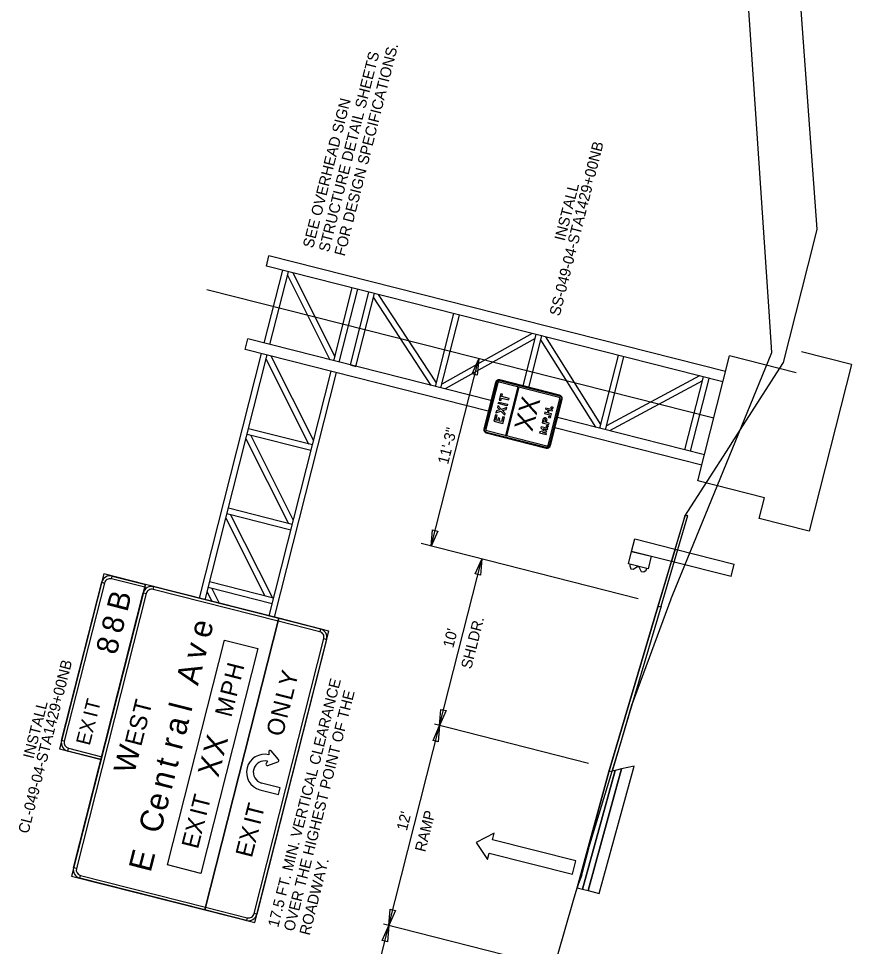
# Model space of a CAD drawing. Extents: x 670003 to 670131, y 737764 to 738002.
# Drawn here: x 670064.8 to 670113.2, y 737890.5 to 737944.5 of the extents above; entities that cross this region are included whole.
import ezdxf

# ---------------------------------------------------------------- set-up
doc = ezdxf.new("R2010")
doc.units = 0
for name, color, linetype in [('R_Alt Surface', 7, 'Continuous'), ('R_Exist Surface', 7, 'Continuous'), ('R_Fin Surface', 7, 'Continuous'), ('R_Guardrail', 7, 'Continuous'), ('R_Horz Alg Annot', 7, 'Continuous'), ('R_MOT', 7, 'Continuous'), ('R_SIGN', 7, 'Continuous'), ('R_SIGN_ANNOT', 7, 'Continuous')]:
    doc.layers.add(name, color=color, linetype=linetype)

msp = doc.modelspace()

# ---------------------------------------------------------------- linework, layer by layer
at = {"layer": 'R_Alt Surface'}
for points in [[(670097.563, 737893.862), (670097.887, 737893.78), (670099.826, 737900.86), (670099.462, 737900.78)], [(670097.887, 737893.78), (670098.533, 737893.617), (670100.555, 737901.019), (670099.826, 737900.86)]]:
    msp.add_lwpolyline(points, close=True, dxfattribs=at)
at = {"layer": 'R_Exist Surface'}
msp.add_lwpolyline([(670096.104, 737889.98), (670097.035, 737893.228), (670097.24, 737893.944), (670097.24, 737893.944), (670097.285, 737894.053), (670097.514, 737894.659), (670097.566, 737894.848), (670097.93, 737896.249), (670097.945, 737896.326), (670098.182, 737897.114), (670099.492, 737901.429), (670099.768, 737902.328), (670100.454, 737904.642), (670100.458, 737904.668), (670102.71, 737910.768), (670102.713, 737910.776), (670102.77, 737910.917), (670108.58, 737925.092), (670108.418, 737927.472), (670107.207, 737945.304)], dxfattribs=at)
at = {"layer": 'R_Fin Surface'}
for points in [[(670097.24, 737893.944), (670099.098, 737900.7), (670101.946, 737910.296), (670103.442, 737915.34), (670103.51, 737915.569), (670106.099, 737919.607), (670106.256, 737919.851), (670109.028, 737924.175), (670109.243, 737924.51), (670111.027, 737931.54), (670111.211, 737932.265), (670109.788, 737951.654), (670109.54, 737955.045)], [(670101.946, 737910.296), (670099.098, 737900.7), (670097.24, 737893.944)]]:
    msp.add_lwpolyline(points, dxfattribs=at)
for points in [[(670101.946, 737910.296), (670102.128, 737910.336), (670103.692, 737915.609), (670103.51, 737915.569)], [(670099.098, 737900.7), (670101.946, 737910.296), (670102.128, 737910.336), (670099.28, 737900.74)], [(670097.24, 737893.944), (670097.563, 737893.862), (670099.462, 737900.78), (670099.098, 737900.7)]]:
    msp.add_lwpolyline(points, close=True, dxfattribs=at)
at = {"layer": 'R_Guardrail'}
for points in [[(670100.412, 737913.522), (670100.596, 737914.249), (670102.942, 737913.654), (670102.729, 737912.935)], [(670100.227, 737912.795), (670100.412, 737913.522), (670101.557, 737913.232), (670101.372, 737912.505)], [(670100.304, 737912.776), (670100.301, 737912.675), (670100.362, 737912.512), (670100.501, 737912.476), (670100.752, 737912.648), (670100.841, 737912.626), (670100.979, 737912.355), (670101.118, 737912.32), (670101.251, 737912.434), (670101.296, 737912.524)]]:
    msp.add_lwpolyline(points, close=True, dxfattribs=at)
for points in [[(670106.199, 737912.055), (670102.729, 737912.935), (670102.942, 737913.654), (670106.383, 737912.782)], [(670106.199, 737912.055), (670106.383, 737912.782)]]:
    msp.add_lwpolyline(points, dxfattribs=at)
at = {"layer": 'R_Horz Alg Annot'}
for p, q in [((670088.751, 737913.823), (670091.517, 737924.728)), ((670100.796, 737910.768), (670088.176, 737913.969)), ((670089.242, 737903.382), (670091.7, 737913.075)), ((670086.291, 737891.75), (670089.242, 737903.382)), ((670097.915, 737901.182), (670088.939, 737903.459)), ((670083.356, 737880.175), (670086.291, 737891.75)), ((670094.965, 737889.55), (670085.989, 737891.827))]:
    msp.add_line(p, q, dxfattribs=at)
for points in [[(670091.135, 737923.857), (670091.517, 737924.728), (670091.438, 737923.781)], [(670089.133, 737914.693), (670088.751, 737913.823), (670088.83, 737914.77)], [(670091.318, 737912.205), (670091.7, 737913.075), (670091.621, 737912.128)], [(670089.623, 737904.252), (670089.242, 737903.382), (670089.321, 737904.329)], [(670088.86, 737902.512), (670089.242, 737903.382), (670089.163, 737902.435)], [(670086.673, 737892.621), (670086.291, 737891.75), (670086.37, 737892.697)], [(670085.91, 737890.88), (670086.291, 737891.75), (670086.212, 737890.803)]]:
    msp.add_lwpolyline(points, close=True, dxfattribs=at)
at = {"layer": 'R_MOT'}
for p, q in [((670092.419, 737897.134), (670091.372, 737896.574)), ((670092.321, 737896.746), (670092.419, 737897.134)), ((670091.372, 737896.574), (670092.026, 737895.583)), ((670097.164, 737895.518), (670092.321, 737896.746)), ((670092.026, 737895.583), (670092.124, 737895.97)), ((670092.124, 737895.97), (670096.967, 737894.742)), ((670096.967, 737894.742), (670097.164, 737895.518))]:
    msp.add_line(p, q, dxfattribs=at)
at = {"layer": 'R_SIGN'}
for p, q in [((670079.164, 737930.117), (670079.318, 737930.723)), ((670105.879, 737923.987), (670079.318, 737930.723)), ((670079.046, 737925.634), (670080.121, 737929.875)), ((670105.725, 737923.381), (670079.164, 737930.117)), ((670079.369, 737925.552), (670080.444, 737929.793)), ((670080.393, 737929.593), (670082.866, 737924.665)), ((670080.707, 737929.726), (670083.148, 737924.861)), ((670083.084, 737924.61), (670084.16, 737928.85)), ((670083.407, 737924.528), (670084.483, 737928.768)), ((670105.187, 737921.261), (670075.695, 737928.74)), ((670084.054, 737924.364), (670085.129, 737928.604)), ((670084.377, 737924.282), (670085.452, 737928.523)), ((670088.761, 737923.17), (670085.397, 737928.303)), ((670089.056, 737923.329), (670085.692, 737928.462)), ((670089.001, 737923.109), (670090.076, 737927.35)), ((670089.324, 737923.027), (670090.399, 737927.268)), ((670094.627, 737926.196), (670089.38, 737923.25)), ((670094.103, 737923.145), (670094.862, 737926.136)), ((670094.426, 737923.063), (670095.185, 737926.054)), ((670077.935, 737925.271), (670078.089, 737925.877)), ((670092.227, 737922.291), (670078.089, 737925.877)), ((670094.805, 737925.913), (670089.559, 737922.968)), ((670098.337, 737920.741), (670095.128, 737925.831)), ((670098.628, 737920.905), (670095.42, 737925.995)), ((670075.281, 737910.791), (670078.892, 737925.028)), ((670092.074, 737921.685), (670077.935, 737925.271)), ((670113.202, 737924.386), (670110.294, 737925.124)), ((670075.604, 737910.709), (670079.215, 737924.946)), ((670079.151, 737924.694), (670081.624, 737919.766)), ((670079.433, 737924.891), (670081.906, 737919.963)), ((670098.572, 737920.682), (670099.647, 737924.922)), ((670098.895, 737920.6), (670099.97, 737924.84)), ((670104.265, 737917.626), (670106.109, 737924.895)), ((670109.986, 737923.912), (670106.109, 737924.895)), ((670079.32, 737909.767), (670082.931, 737924.004)), ((670079.643, 737909.685), (670083.254, 737923.922)), ((670084.054, 737924.364), (670084.377, 737924.282)), ((670113.202, 737924.386), (670110.743, 737914.693)), ((670096.196, 737922.478), (670092.706, 737923.363)), ((670096.216, 737922.558), (670092.726, 737923.444)), ((670092.736, 737923.484), (670092.736, 737923.484)), ((670096.226, 737922.599), (670092.736, 737923.484)), ((670096.228, 737922.606), (670092.738, 737923.492)), ((670104.355, 737923.728), (670098.95, 737920.819)), ((670104.538, 737923.448), (670099.134, 737920.539)), ((670103.519, 737919.427), (670104.594, 737923.668)), ((670103.842, 737919.345), (670104.917, 737923.586)), ((670092.496, 737923.349), (670091.813, 737920.657)), ((670092.504, 737923.346), (670091.821, 737920.655)), ((670092.544, 737923.336), (670091.861, 737920.644)), ((670092.625, 737923.316), (670091.942, 737920.624)), ((670092.504, 737923.346), (670092.504, 737923.346)), ((670093.794, 737923.087), (670093.079, 737920.267)), ((670093.794, 737923.087), (670093.079, 737920.267)), ((670093.794, 737923.087), (670093.079, 737920.267)), ((670093.16, 737920.247), (670093.875, 737923.067)), ((670093.16, 737920.247), (670093.875, 737923.067)), ((670093.16, 737920.247), (670093.875, 737923.067)), ((670093.875, 737923.067), (670093.794, 737923.087)), ((670093.875, 737923.067), (670093.794, 737923.087)), ((670093.875, 737923.067), (670093.794, 737923.087)), ((670096.228, 737922.606), (670093.867, 737923.205)), ((670095.562, 737919.707), (670096.244, 737922.398)), ((670095.642, 737919.686), (670096.325, 737922.377)), ((670095.683, 737919.675), (670096.365, 737922.367)), ((670095.691, 737919.673), (670096.373, 737922.365)), ((670096.226, 737922.599), (670096.226, 737922.598)), ((670096.365, 737922.367), (670096.365, 737922.367)), ((670104.649, 737919.14), (670096.105, 737921.307)), ((670091.821, 737920.655), (670091.821, 737920.655)), ((670095.421, 737921.154), (670095.39, 737921.029)), ((670095.458, 737921.012), (670095.489, 737921.137)), ((670104.496, 737918.534), (670095.943, 737920.703)), ((670081.758, 737919.382), (670078.043, 737920.324)), ((670081.842, 737919.711), (670078.126, 737920.653)), ((670078.261, 737920.269), (670080.733, 737915.341)), ((670091.958, 737920.415), (670095.448, 737919.53)), ((670091.96, 737920.423), (670095.45, 737919.538)), ((670091.96, 737920.423), (670091.96, 737920.423)), ((670091.97, 737920.463), (670095.46, 737919.578)), ((670091.991, 737920.543), (670095.48, 737919.658)), ((670093.079, 737920.267), (670093.16, 737920.247)), ((670093.079, 737920.267), (670093.16, 737920.247)), ((670093.079, 737920.267), (670093.16, 737920.247)), ((670077.979, 737920.072), (670080.452, 737915.144)), ((670095.642, 737919.686), (670095.561, 737919.706)), ((670095.562, 737919.707), (670095.642, 737919.686)), ((670095.691, 737919.673), (670095.683, 737919.675)), ((670095.683, 737919.675), (670095.683, 737919.675)), ((670095.683, 737919.675), (670095.691, 737919.673)), ((670095.45, 737919.538), (670095.45, 737919.538)), ((670108.143, 737916.642), (670104.265, 737917.626)), ((670107.835, 737915.431), (670108.143, 737916.642)), ((670080.67, 737915.089), (670076.954, 737916.031)), ((670076.806, 737915.45), (670079.078, 737910.924)), ((670080.586, 737914.759), (670076.87, 737915.702)), ((670077.088, 737915.646), (670079.514, 737910.813)), ((670110.743, 737914.693), (670107.835, 737915.431)), ((670069.708, 737912.205), (670067.126, 737902.027)), ((670072.131, 737911.59), (670069.708, 737912.205)), ((670070.151, 737911.92), (670070.192, 737912.082)), ((670072.131, 737911.59), (670067.829, 737894.627)), ((670069.55, 737901.413), (670072.131, 737911.59)), ((670069.585, 737911.72), (670069.746, 737911.679)), ((670079.885, 737909.624), (670072.131, 737911.59)), ((670079.581, 737910.796), (670075.865, 737911.739)), ((670072.008, 737911.106), (670072.169, 737911.065)), ((670072.575, 737911.306), (670072.615, 737911.467)), ((670075.718, 737911.157), (670075.992, 737910.611)), ((670079.497, 737910.467), (670075.782, 737911.409)), ((670076, 737911.354), (670076.428, 737910.501)), ((670075.583, 737892.661), (670079.885, 737909.624)), ((670079.885, 737909.624), (670075.583, 737892.661)), ((670082.793, 737908.886), (670079.885, 737909.624)), ((670078.491, 737891.923), (670082.793, 737908.886)), ((670082.309, 737909.009), (670082.268, 737908.847)), ((670073.409, 737895.275), (670076.728, 737908.361)), ((670076.728, 737908.361), (670078.667, 737907.869)), ((670082.509, 737908.442), (670082.67, 737908.401)), ((670078.667, 737907.869), (670075.348, 737894.784)), ((670067.411, 737902.471), (670067.249, 737902.512)), ((670067.126, 737902.027), (670069.55, 737901.413)), ((670067.611, 737901.904), (670067.652, 737902.066)), ((670079.301, 737901.855), (670079.31, 737901.684)), ((670079.301, 737901.855), (670079.31, 737901.684)), ((670079.875, 737901.404), (670079.439, 737901.91)), ((670079.875, 737901.404), (670079.439, 737901.91)), ((670069.55, 737901.413), (670069.55, 737901.413)), ((670079.229, 737901.307), (670079.149, 737901.183)), ((670079.229, 737901.307), (670079.149, 737901.183)), ((670079.242, 737901.066), (670079.842, 737901.279)), ((670079.242, 737901.066), (670079.842, 737901.279)), ((670078.788, 737899.653), (670079.876, 737899.377)), ((670078.788, 737899.653), (670079.876, 737899.377)), ((670079.974, 737899.761), (670078.885, 737900.037)), ((670079.974, 737899.761), (670078.885, 737900.037)), ((670079.876, 737899.377), (670079.974, 737899.761)), ((670079.876, 737899.377), (670079.974, 737899.761)), ((670068.113, 737895.071), (670067.952, 737895.112)), ((670075.348, 737894.784), (670073.409, 737895.275)), ((670067.829, 737894.627), (670075.583, 737892.661)), ((670068.313, 737894.504), (670068.354, 737894.666)), ((670075.422, 737892.702), (670070.898, 737893.849)), ((670075.583, 737892.661), (670075.583, 737892.661)), ((670075.583, 737892.661), (670078.491, 737891.923)), ((670078.047, 737892.208), (670078.006, 737892.046)), ((670078.614, 737892.408), (670078.452, 737892.449)), ((670078.491, 737891.923), (670078.491, 737891.923))]:
    msp.add_line(p, q, dxfattribs=at)
for points in [[(670092.8, 737922.291), (670092.836, 737922.435), (670093.263, 737922.327), (670093.285, 737922.415), (670092.859, 737922.523), (670092.895, 737922.667), (670092.805, 737922.69), (670092.709, 737922.314)], [(670092.8, 737922.291), (670092.836, 737922.435), (670093.263, 737922.327), (670093.285, 737922.415), (670092.859, 737922.523), (670092.895, 737922.667), (670092.805, 737922.69), (670092.709, 737922.314)], [(670092.8, 737922.291), (670092.836, 737922.435), (670093.263, 737922.327), (670093.285, 737922.415), (670092.859, 737922.523), (670092.895, 737922.667), (670092.805, 737922.69), (670092.709, 737922.314)], [(670093.038, 737921.44), (670093.064, 737921.545), (670092.908, 737921.708), (670093.123, 737921.777), (670093.15, 737921.882), (670092.837, 737921.782), (670092.629, 737921.999), (670092.603, 737921.894), (670092.74, 737921.75), (670092.551, 737921.69), (670092.524, 737921.585), (670092.811, 737921.677)], [(670093.038, 737921.44), (670093.064, 737921.545), (670092.908, 737921.708), (670093.123, 737921.777), (670093.15, 737921.882), (670092.837, 737921.782), (670092.629, 737921.999), (670092.603, 737921.894), (670092.74, 737921.75), (670092.551, 737921.69), (670092.524, 737921.585), (670092.811, 737921.677)], [(670093.038, 737921.44), (670093.064, 737921.545), (670092.908, 737921.708), (670093.123, 737921.777), (670093.15, 737921.882), (670092.837, 737921.782), (670092.629, 737921.999), (670092.603, 737921.894), (670092.74, 737921.75), (670092.551, 737921.69), (670092.524, 737921.585), (670092.811, 737921.677)], [(670093.177, 737921.988), (670092.66, 737922.119), (670092.682, 737922.208), (670093.199, 737922.076)], [(670093.177, 737921.988), (670092.66, 737922.119), (670092.682, 737922.208), (670093.199, 737922.076)], [(670093.177, 737921.988), (670092.66, 737922.119), (670092.682, 737922.208), (670093.199, 737922.076)], [(670095.553, 737921.75), (670095.509, 737921.575), (670095.357, 737921.614), (670095.341, 737921.547), (670095.728, 737921.449), (670095.745, 737921.515), (670095.577, 737921.558), (670095.621, 737921.732), (670095.789, 737921.69), (670095.806, 737921.756), (670095.418, 737921.854), (670095.402, 737921.788)], [(670095.553, 737921.75), (670095.509, 737921.575), (670095.357, 737921.614), (670095.341, 737921.547), (670095.728, 737921.449), (670095.745, 737921.515), (670095.577, 737921.558), (670095.621, 737921.732), (670095.789, 737921.69), (670095.806, 737921.756), (670095.418, 737921.854), (670095.402, 737921.788)], [(670095.553, 737921.75), (670095.509, 737921.575), (670095.357, 737921.614), (670095.341, 737921.547), (670095.728, 737921.449), (670095.745, 737921.515), (670095.577, 737921.558), (670095.621, 737921.732), (670095.789, 737921.69), (670095.806, 737921.756), (670095.418, 737921.854), (670095.402, 737921.788)], [(670092.92, 737921.356), (670092.847, 737921.068), (670092.703, 737921.105), (670092.742, 737921.257), (670092.651, 737921.28), (670092.613, 737921.128), (670092.511, 737921.153), (670092.584, 737921.441), (670092.494, 737921.464), (670092.398, 737921.088), (670092.915, 737920.957), (670093.011, 737921.333)], [(670092.92, 737921.356), (670092.847, 737921.068), (670092.703, 737921.105), (670092.742, 737921.257), (670092.651, 737921.28), (670092.613, 737921.128), (670092.511, 737921.153), (670092.584, 737921.441), (670092.494, 737921.464), (670092.398, 737921.088), (670092.915, 737920.957), (670093.011, 737921.333)], [(670092.92, 737921.356), (670092.847, 737921.068), (670092.703, 737921.105), (670092.742, 737921.257), (670092.651, 737921.28), (670092.613, 737921.128), (670092.511, 737921.153), (670092.584, 737921.441), (670092.494, 737921.464), (670092.398, 737921.088), (670092.915, 737920.957), (670093.011, 737921.333)], [(670095.225, 737920.445), (670095.487, 737920.496), (670095.281, 737920.666), (670095.515, 737920.607), (670095.532, 737920.673), (670095.144, 737920.772), (670095.127, 737920.705), (670095.331, 737920.535), (670095.071, 737920.484), (670095.054, 737920.417), (670095.442, 737920.319), (670095.459, 737920.385)], [(670095.225, 737920.445), (670095.487, 737920.496), (670095.281, 737920.666), (670095.515, 737920.607), (670095.532, 737920.673), (670095.144, 737920.772), (670095.127, 737920.705), (670095.331, 737920.535), (670095.071, 737920.484), (670095.054, 737920.417), (670095.442, 737920.319), (670095.459, 737920.385)], [(670095.225, 737920.445), (670095.487, 737920.496), (670095.281, 737920.666), (670095.515, 737920.607), (670095.532, 737920.673), (670095.144, 737920.772), (670095.127, 737920.705), (670095.331, 737920.535), (670095.071, 737920.484), (670095.054, 737920.417), (670095.442, 737920.319), (670095.459, 737920.385)], [(670072.09, 737911.429), (670070.151, 737911.92), (670070.192, 737912.082), (670072.131, 737911.59), (670072.09, 737911.429)], [(670069.746, 737911.679), (670067.411, 737902.471), (670067.249, 737902.512), (670069.585, 737911.72), (670069.746, 737911.679)], [(670072.169, 737911.065), (670068.113, 737895.071), (670067.952, 737895.112), (670072.008, 737911.106), (670072.169, 737911.065)], [(670079.844, 737909.462), (670072.575, 737911.306), (670072.615, 737911.467), (670079.885, 737909.624), (670079.844, 737909.462)], [(670082.268, 737908.847), (670079.844, 737909.462), (670079.885, 737909.624), (670082.309, 737909.009), (670082.268, 737908.847)], [(670078.452, 737892.449), (670082.509, 737908.442), (670082.67, 737908.401), (670078.614, 737892.408), (670078.452, 737892.449)], [(670067.652, 737902.066), (670069.59, 737901.574), (670069.55, 737901.413), (670067.611, 737901.904), (670067.652, 737902.066)], [(670068.354, 737894.666), (670075.624, 737892.822), (670075.583, 737892.661), (670068.313, 737894.504), (670068.354, 737894.666)], [(670075.624, 737892.822), (670078.047, 737892.208), (670078.006, 737892.046), (670075.583, 737892.661), (670075.624, 737892.822)]]:
    msp.add_lwpolyline(points, close=True, dxfattribs=at)
for points in [[(670095.252, 737921.197), (670095.203, 737921.006), (670095.591, 737920.908), (670095.608, 737920.974), (670095.458, 737921.012)], [(670095.252, 737921.197), (670095.22, 737921.072), (670095.288, 737921.055), (670095.32, 737921.18)], [(670095.252, 737921.197), (670095.22, 737921.072), (670095.288, 737921.055), (670095.32, 737921.18)], [(670095.22, 737921.072), (670095.203, 737921.006), (670095.591, 737920.908), (670095.608, 737920.974), (670095.458, 737921.012), (670095.489, 737921.137)], [(670095.22, 737921.072), (670095.203, 737921.006), (670095.591, 737920.908), (670095.608, 737920.974), (670095.458, 737921.012), (670095.489, 737921.137)], [(670095.421, 737921.154), (670095.39, 737921.029), (670095.22, 737921.072)], [(670095.421, 737921.154), (670095.39, 737921.029), (670095.22, 737921.072)], [(670095.39, 737921.029), (670095.288, 737921.055), (670095.32, 737921.18)]]:
    msp.add_lwpolyline(points, dxfattribs=at)
for centre, radius, start, end in [((670070.069, 737911.597), 0.5, 75.7686, 165.7688), ((670070.069, 737911.597), 0.333, 75.7686, 165.7688), ((670072.493, 737910.983), 0.5, 75.7686, 165.7688), ((670072.493, 737910.983), 0.333, 75.7686, 165.7688), ((670082.186, 737908.524), 0.333, 345.7686, 75.7688), ((670082.186, 737908.524), 0.5, 345.7686, 75.7688), ((670067.734, 737902.389), 0.5, 165.7688, 255.7684), ((670067.734, 737902.389), 0.333, 165.7688, 255.7684), ((670079.379, 737901.859), 0.0785, 40.7767, 183.2283), ((670079.379, 737901.859), 0.0785, 40.7767, 183.2283), ((670079.06, 737900.666), 1.049, 76.1684, 254.9793), ((670079.06, 737900.666), 1.049, 76.1684, 254.9793), ((670079.063, 737900.671), 0.658, 75.3868, 254.3334), ((670079.063, 737900.671), 0.658, 75.3868, 254.3334), ((670079.816, 737901.353), 0.0785, 289.4736, 40.7767), ((670079.816, 737901.353), 0.0785, 289.4736, 40.7767), ((670079.216, 737901.14), 0.0785, 147.5362, 289.4736), ((670079.216, 737901.14), 0.0785, 147.5362, 289.4736), ((670068.436, 737894.989), 0.5, 165.7688, 255.7684), ((670068.436, 737894.989), 0.333, 165.7688, 255.7684), ((670078.129, 737892.531), 0.5, 255.7684, 345.7686), ((670078.129, 737892.531), 0.333, 255.7684, 345.7686)]:
    msp.add_arc(centre, radius, start, end, dxfattribs=at)
for centre, major_axis, ratio, start_param, end_param in [((670092.69, 737923.299), (-0.194, 0.049), 0.991667, 4.712389, 6.283185), ((670092.69, 737923.299), (-0.186, 0.047), 0.991667, 4.712389, 6.283185), ((670092.69, 737923.299), (-0.145, 0.037), 0.991667, 4.712389, 6.283185), ((670092.69, 737923.299), (-0.0646, 0.0164), 0.991667, 4.712389, 6.283185), ((670096.179, 737922.414), (-0.0646, 0.0164), 0.991667, 3.141593, 4.712389), ((670096.179, 737922.414), (-0.145, 0.037), 0.991667, 3.141593, 4.712389), ((670096.179, 737922.414), (-0.186, 0.047), 0.991667, 3.141593, 4.712389), ((670096.179, 737922.414), (-0.194, 0.049), 0.991667, 3.141593, 4.712389), ((670095.371, 737921.167), (-0.119, 0.03), 0.976792, 3.141593, 6.283185), ((670095.371, 737921.167), (-0.119, 0.03), 0.976792, 3.141593, 6.283185), ((670095.371, 737921.167), (-0.119, 0.03), 0.976792, 3.141593, 6.283185), ((670095.371, 737921.167), (-0.0509, 0.0129), 0.976792, 3.141593, 6.283185), ((670095.371, 737921.167), (-0.0509, 0.0129), 0.976792, 3.141593, 6.283185), ((670095.371, 737921.167), (-0.0509, 0.0129), 0.976792, 3.141593, 6.283185), ((670092.007, 737920.608), (-0.194, 0.049), 0.991667, 0, 1.570796), ((670092.007, 737920.608), (-0.186, 0.047), 0.991667, 0, 1.570796), ((670092.007, 737920.608), (-0.145, 0.037), 0.991667, 0, 1.570796), ((670092.007, 737920.608), (-0.0646, 0.0164), 0.991667, 0, 1.570796), ((670095.497, 737919.722), (-0.194, 0.049), 0.991667, 1.570796, 3.141593), ((670095.497, 737919.722), (-0.186, 0.047), 0.991667, 1.570796, 3.141593), ((670095.497, 737919.722), (-0.145, 0.037), 0.991667, 1.570796, 3.141593), ((670095.497, 737919.722), (-0.0646, 0.0164), 0.991667, 1.570796, 3.141593)]:
    msp.add_ellipse(centre, major_axis=major_axis, ratio=ratio, start_param=start_param, end_param=end_param, dxfattribs=at)
for centre in [(670095.777, 737921.875), (670095.777, 737921.875), (670095.777, 737921.875), (670095.64, 737921.334), (670095.64, 737921.334), (670095.64, 737921.334), (670095.503, 737920.792), (670095.503, 737920.792), (670095.503, 737920.792)]:
    msp.add_ellipse(centre, major_axis=(-0.0554, 0.0141), ratio=0.991667, dxfattribs=at)

# ---------------------------------------------------------------- texts
at = {"layer": 'R_Horz Alg Annot'}
for s, p in [('11\'-3"', (670089.732, 737918.544)), ("10'", (670090.036, 737907.867)), ("12'", (670087.337, 737897.228))]:
    msp.add_text(s, height=0.63, rotation=75.7686, dxfattribs=at).set_placement(p)
at = {"layer": 'R_SIGN'}
for s, height, p in [('XX', 1.098, (670094.634, 737920.449)), ('B', 1.25, (670071.071, 737909.955)), ('8', 1.25, (670070.749, 737908.683)), ('e', 1.333, (670075.877, 737908.395)), ('8', 1.25, (670070.438, 737907.459)), ('v', 1.333, (670075.559, 737907.141)), ('A', 1.333, (670075.185, 737905.668)), ('H', 1, (670077.665, 737905.954)), ('Y', 1, (670080.836, 737905.575)), ('P', 1, (670077.422, 737904.995)), ('M', 1, (670077.124, 737903.822)), ('L', 1, (670080.639, 737904.8)), ('T', 0.833, (670069.383, 737904.146)), ('T', 1, (670072.343, 737903.953)), ('l', 1.333, (670074.792, 737904.117)), ('N', 1, (670080.371, 737903.743)), ('I', 0.833, (670069.299, 737903.814)), ('S', 1, (670072.107, 737903.022)), ('X', 0.833, (670069.07, 737902.913)), ('a', 1.333, (670074.444, 737902.747)), ('O', 1, (670080.106, 737902.696)), ('E', 0.833, (670068.885, 737902.183)), ('E', 1, (670071.881, 737902.131)), ('X', 1.25, (670076.68, 737901.562)), ('W', 1.25, (670071.473, 737900.523)), ('r', 1.333, (670074.231, 737901.907)), ('t', 1.333, (670073.956, 737900.821)), ('X', 1.25, (670076.367, 737900.326)), ('n', 1.333, (670073.645, 737899.593)), ('e', 1.333, (670073.327, 737898.34)), ('T', 1, (670075.756, 737898.428)), ('I', 1, (670075.663, 737898.059)), ('T', 1, (670078.894, 737897.92)), ('C', 1.333, (670072.999, 737897.047)), ('X', 1, (670075.397, 737897.012)), ('I', 1, (670078.801, 737897.552)), ('X', 1, (670078.535, 737896.505)), ('E', 1, (670075.181, 737896.159)), ('E', 1, (670078.319, 737895.652)), ('E', 1.333, (670072.429, 737894.798))]:
    msp.add_text(s, height=height, rotation=75.7686, dxfattribs=at).set_placement(p)
at = {"layer": 'R_SIGN_ANNOT'}
for s, p in [('FOR DESIGN SPECIFICATIONS.', (670083.717, 737930.661)), ('STRUCTURE DETAIL SHEETS ', (670082.801, 737930.894)), ('SEE OVERHEAD SIGN ', (670081.885, 737931.126)), ('SS-049-04-STA1429+00NB', (670096.229, 737927.178)), ('INSTALL', (670096.522, 737931.544)), ('SHLDR.', (670091.084, 737906.64)), ('CL-049-04-STA1429+00NB', (670065.323, 737897.064)), ('17.5 FT. MIN. VERTICAL CLEARANCE ', (670079.852, 737891.608)), ('OVER THE HIGHEST POINT OF THE ', (670080.768, 737891.376)), ('INSTALL', (670065.612, 737901.415)), ('RAMP', (670088.405, 737895.993)), ('ROADWAY.', (670081.684, 737891.144))]:
    msp.add_text(s, height=0.63, rotation=75.7686, dxfattribs=at).set_placement(p)

doc.saveas('drawing.dxf')
